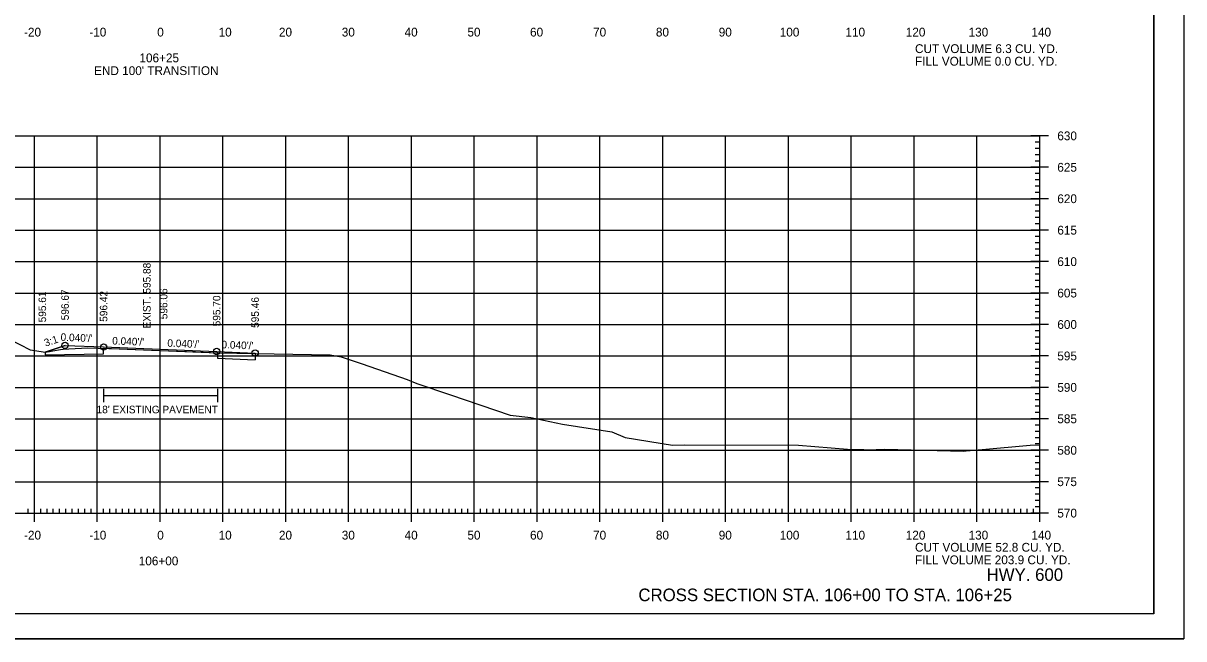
# Model space of a CAD drawing. Extents: x 961436 to 1372525, y 380079 to 2027791.
# Drawn here: x 1371173.1 to 1371357.8, y 380749.1 to 380847 of the extents above; entities that cross this region are included whole.
import ezdxf

# ---------------------------------------------------------------- set-up
doc = ezdxf.new("R2010")
doc.units = 0
for name, color, linetype in [('R_Alt Surface', 7, 'Continuous'), ('R_Axis', 7, 'Continuous'), ('R_Axis Annot', 7, 'Continuous'), ('R_Border', 7, 'Continuous'), ('R_Draft', 7, 'Continuous'), ('R_Drive', 7, 'Continuous'), ('R_Exist Surface', 7, 'Continuous'), ('R_Fin Surface', 7, 'Continuous'), ('R_Fin Surface Annot', 7, 'Continuous'), ('R_Grid', 7, 'Continuous'), ('R_No Plot', 7, 'Continuous'), ('R_Xsect Elev', 7, 'Continuous')]:
    doc.layers.add(name, color=color, linetype=linetype)

msp = doc.modelspace()

# ---------------------------------------------------------------- linework, layer by layer
at = {"layer": 'R_Alt Surface'}
for p, q in [((1371176.58, 380794.68), (1371176.58, 380794.23)), ((1371210, 380794.53), (1371210, 380793.45))]:
    msp.add_line(p, q, dxfattribs=at)
for points in [[(1371179.75, 380795.74), (1371176.58, 380794.68)], [(1371176.58, 380794.23), (1371185.86, 380794.41), (1371185.86, 380795.29), (1371194.88, 380794.95), (1371203.99, 380794.57), (1371203.99, 380793.69), (1371210, 380793.45)], [(1371210, 380794.53), (1371210, 380793.45)]]:
    msp.add_lwpolyline(points, dxfattribs=at)
at = {"layer": 'R_Axis'}
for p, q in [((1371336.28, 380829.07), (1371333.48, 380829.07)), ((1371334.88, 380769.07), (1371334.88, 380829.07)), ((1371334.88, 380828.07), (1371334.18, 380828.07)), ((1371334.88, 380827.07), (1371334.18, 380827.07)), ((1371334.88, 380826.07), (1371334.18, 380826.07)), ((1371336.28, 380824.07), (1371333.48, 380824.07)), ((1371334.88, 380825.07), (1371334.18, 380825.07)), ((1371334.88, 380823.07), (1371334.18, 380823.07)), ((1371334.88, 380822.07), (1371334.18, 380822.07)), ((1371334.88, 380821.07), (1371334.18, 380821.07)), ((1371334.88, 380820.07), (1371334.18, 380820.07)), ((1371336.28, 380819.07), (1371333.48, 380819.07)), ((1371334.88, 380818.07), (1371334.18, 380818.07)), ((1371334.88, 380817.07), (1371334.18, 380817.07)), ((1371334.88, 380816.07), (1371334.18, 380816.07)), ((1371334.88, 380815.07), (1371334.18, 380815.07)), ((1371336.28, 380814.07), (1371333.48, 380814.07)), ((1371334.88, 380813.07), (1371334.18, 380813.07)), ((1371334.88, 380812.07), (1371334.18, 380812.07)), ((1371334.88, 380811.07), (1371334.18, 380811.07)), ((1371336.28, 380809.07), (1371333.48, 380809.07)), ((1371334.88, 380810.07), (1371334.18, 380810.07)), ((1371334.88, 380808.07), (1371334.18, 380808.07)), ((1371334.88, 380807.07), (1371334.18, 380807.07)), ((1371334.88, 380806.07), (1371334.18, 380806.07)), ((1371334.88, 380805.07), (1371334.18, 380805.07)), ((1371336.28, 380804.07), (1371333.48, 380804.07)), ((1371334.88, 380803.07), (1371334.18, 380803.07)), ((1371334.88, 380802.07), (1371334.18, 380802.07)), ((1371334.88, 380801.07), (1371334.18, 380801.07)), ((1371334.88, 380800.07), (1371334.18, 380800.07)), ((1371336.28, 380799.07), (1371333.48, 380799.07)), ((1371334.88, 380798.07), (1371334.18, 380798.07)), ((1371334.88, 380797.07), (1371334.18, 380797.07)), ((1371334.88, 380796.07), (1371334.18, 380796.07)), ((1371336.28, 380794.07), (1371333.48, 380794.07)), ((1371334.88, 380795.07), (1371334.18, 380795.07)), ((1371334.88, 380793.07), (1371334.18, 380793.07)), ((1371334.88, 380792.07), (1371334.18, 380792.07)), ((1371334.88, 380791.07), (1371334.18, 380791.07)), ((1371336.28, 380789.07), (1371333.48, 380789.07)), ((1371334.88, 380790.07), (1371334.18, 380790.07)), ((1371334.88, 380788.07), (1371334.18, 380788.07)), ((1371334.88, 380787.07), (1371334.18, 380787.07)), ((1371334.88, 380786.07), (1371334.18, 380786.07)), ((1371334.88, 380785.07), (1371334.18, 380785.07)), ((1371336.28, 380784.07), (1371333.48, 380784.07)), ((1371334.88, 380783.07), (1371334.18, 380783.07)), ((1371334.88, 380782.07), (1371334.18, 380782.07)), ((1371334.88, 380781.07), (1371334.18, 380781.07)), ((1371336.28, 380779.07), (1371333.48, 380779.07)), ((1371334.88, 380780.07), (1371334.18, 380780.07)), ((1371334.88, 380778.07), (1371334.18, 380778.07)), ((1371334.88, 380777.07), (1371334.18, 380777.07)), ((1371334.88, 380776.07), (1371334.18, 380776.07)), ((1371336.28, 380774.07), (1371333.48, 380774.07)), ((1371334.88, 380775.07), (1371334.18, 380775.07)), ((1371334.88, 380773.07), (1371334.18, 380773.07)), ((1371334.88, 380772.07), (1371334.18, 380772.07)), ((1371174.88, 380767.67), (1371174.88, 380770.47)), ((1371184.88, 380767.67), (1371184.88, 380770.47)), ((1371194.88, 380767.67), (1371194.88, 380770.47)), ((1371204.88, 380767.67), (1371204.88, 380770.47)), ((1371214.88, 380767.67), (1371214.88, 380770.47)), ((1371224.88, 380767.67), (1371224.88, 380770.47)), ((1371234.88, 380767.67), (1371234.88, 380770.47)), ((1371244.88, 380767.67), (1371244.88, 380770.47)), ((1371254.88, 380767.67), (1371254.88, 380770.47)), ((1371264.88, 380767.67), (1371264.88, 380770.47)), ((1371274.88, 380767.67), (1371274.88, 380770.47)), ((1371284.88, 380767.67), (1371284.88, 380770.47)), ((1371294.88, 380767.67), (1371294.88, 380770.47)), ((1371304.88, 380767.67), (1371304.88, 380770.47)), ((1371314.88, 380767.67), (1371314.88, 380770.47)), ((1371324.88, 380767.67), (1371324.88, 380770.47)), ((1371334.88, 380771.07), (1371334.18, 380771.07)), ((1371334.88, 380770.07), (1371334.18, 380770.07)), ((1371334.88, 380767.67), (1371334.88, 380770.47)), ((1371054.88, 380769.07), (1371334.88, 380769.07)), ((1371173.88, 380769.07), (1371173.88, 380769.77)), ((1371175.88, 380769.07), (1371175.88, 380769.77)), ((1371176.88, 380769.07), (1371176.88, 380769.77)), ((1371177.88, 380769.07), (1371177.88, 380769.77)), ((1371178.88, 380769.07), (1371178.88, 380769.77)), ((1371179.88, 380769.07), (1371179.88, 380769.77)), ((1371180.88, 380769.07), (1371180.88, 380769.77)), ((1371181.88, 380769.07), (1371181.88, 380769.77)), ((1371182.88, 380769.07), (1371182.88, 380769.77)), ((1371183.88, 380769.07), (1371183.88, 380769.77)), ((1371185.88, 380769.07), (1371185.88, 380769.77)), ((1371186.88, 380769.07), (1371186.88, 380769.77)), ((1371187.88, 380769.07), (1371187.88, 380769.77)), ((1371188.88, 380769.07), (1371188.88, 380769.77)), ((1371189.88, 380769.07), (1371189.88, 380769.77)), ((1371190.88, 380769.07), (1371190.88, 380769.77)), ((1371191.88, 380769.07), (1371191.88, 380769.77)), ((1371192.88, 380769.07), (1371192.88, 380769.77)), ((1371193.88, 380769.07), (1371193.88, 380769.77)), ((1371195.88, 380769.07), (1371195.88, 380769.77)), ((1371196.88, 380769.07), (1371196.88, 380769.77)), ((1371197.88, 380769.07), (1371197.88, 380769.77)), ((1371198.88, 380769.07), (1371198.88, 380769.77)), ((1371199.88, 380769.07), (1371199.88, 380769.77)), ((1371200.88, 380769.07), (1371200.88, 380769.77)), ((1371201.88, 380769.07), (1371201.88, 380769.77)), ((1371202.88, 380769.07), (1371202.88, 380769.77)), ((1371203.88, 380769.07), (1371203.88, 380769.77)), ((1371205.88, 380769.07), (1371205.88, 380769.77)), ((1371206.88, 380769.07), (1371206.88, 380769.77)), ((1371207.88, 380769.07), (1371207.88, 380769.77)), ((1371208.88, 380769.07), (1371208.88, 380769.77)), ((1371209.88, 380769.07), (1371209.88, 380769.77)), ((1371210.88, 380769.07), (1371210.88, 380769.77)), ((1371211.88, 380769.07), (1371211.88, 380769.77)), ((1371212.88, 380769.07), (1371212.88, 380769.77)), ((1371213.88, 380769.07), (1371213.88, 380769.77)), ((1371215.88, 380769.07), (1371215.88, 380769.77)), ((1371216.88, 380769.07), (1371216.88, 380769.77)), ((1371217.88, 380769.07), (1371217.88, 380769.77)), ((1371218.88, 380769.07), (1371218.88, 380769.77)), ((1371219.88, 380769.07), (1371219.88, 380769.77)), ((1371220.88, 380769.07), (1371220.88, 380769.77)), ((1371221.88, 380769.07), (1371221.88, 380769.77)), ((1371222.88, 380769.07), (1371222.88, 380769.77)), ((1371223.88, 380769.07), (1371223.88, 380769.77)), ((1371225.88, 380769.07), (1371225.88, 380769.77)), ((1371226.88, 380769.07), (1371226.88, 380769.77)), ((1371227.88, 380769.07), (1371227.88, 380769.77)), ((1371228.88, 380769.07), (1371228.88, 380769.77)), ((1371229.88, 380769.07), (1371229.88, 380769.77)), ((1371230.88, 380769.07), (1371230.88, 380769.77)), ((1371231.88, 380769.07), (1371231.88, 380769.77)), ((1371232.88, 380769.07), (1371232.88, 380769.77)), ((1371233.88, 380769.07), (1371233.88, 380769.77)), ((1371235.88, 380769.07), (1371235.88, 380769.77)), ((1371236.88, 380769.07), (1371236.88, 380769.77)), ((1371237.88, 380769.07), (1371237.88, 380769.77)), ((1371238.88, 380769.07), (1371238.88, 380769.77)), ((1371239.88, 380769.07), (1371239.88, 380769.77)), ((1371240.88, 380769.07), (1371240.88, 380769.77)), ((1371241.88, 380769.07), (1371241.88, 380769.77)), ((1371242.88, 380769.07), (1371242.88, 380769.77)), ((1371243.88, 380769.07), (1371243.88, 380769.77)), ((1371245.88, 380769.07), (1371245.88, 380769.77)), ((1371246.88, 380769.07), (1371246.88, 380769.77)), ((1371247.88, 380769.07), (1371247.88, 380769.77)), ((1371248.88, 380769.07), (1371248.88, 380769.77)), ((1371249.88, 380769.07), (1371249.88, 380769.77)), ((1371250.88, 380769.07), (1371250.88, 380769.77)), ((1371251.88, 380769.07), (1371251.88, 380769.77)), ((1371252.88, 380769.07), (1371252.88, 380769.77)), ((1371253.88, 380769.07), (1371253.88, 380769.77)), ((1371255.88, 380769.07), (1371255.88, 380769.77)), ((1371256.88, 380769.07), (1371256.88, 380769.77)), ((1371257.88, 380769.07), (1371257.88, 380769.77)), ((1371258.88, 380769.07), (1371258.88, 380769.77)), ((1371259.88, 380769.07), (1371259.88, 380769.77)), ((1371260.88, 380769.07), (1371260.88, 380769.77)), ((1371261.88, 380769.07), (1371261.88, 380769.77)), ((1371262.88, 380769.07), (1371262.88, 380769.77)), ((1371263.88, 380769.07), (1371263.88, 380769.77)), ((1371265.88, 380769.07), (1371265.88, 380769.77)), ((1371266.88, 380769.07), (1371266.88, 380769.77)), ((1371267.88, 380769.07), (1371267.88, 380769.77)), ((1371268.88, 380769.07), (1371268.88, 380769.77)), ((1371269.88, 380769.07), (1371269.88, 380769.77)), ((1371270.88, 380769.07), (1371270.88, 380769.77)), ((1371271.88, 380769.07), (1371271.88, 380769.77)), ((1371272.88, 380769.07), (1371272.88, 380769.77)), ((1371273.88, 380769.07), (1371273.88, 380769.77)), ((1371275.88, 380769.07), (1371275.88, 380769.77)), ((1371276.88, 380769.07), (1371276.88, 380769.77)), ((1371277.88, 380769.07), (1371277.88, 380769.77)), ((1371278.88, 380769.07), (1371278.88, 380769.77)), ((1371279.88, 380769.07), (1371279.88, 380769.77)), ((1371280.88, 380769.07), (1371280.88, 380769.77)), ((1371281.88, 380769.07), (1371281.88, 380769.77)), ((1371282.88, 380769.07), (1371282.88, 380769.77)), ((1371283.88, 380769.07), (1371283.88, 380769.77)), ((1371285.88, 380769.07), (1371285.88, 380769.77)), ((1371286.88, 380769.07), (1371286.88, 380769.77)), ((1371287.88, 380769.07), (1371287.88, 380769.77)), ((1371288.88, 380769.07), (1371288.88, 380769.77)), ((1371289.88, 380769.07), (1371289.88, 380769.77)), ((1371290.88, 380769.07), (1371290.88, 380769.77)), ((1371291.88, 380769.07), (1371291.88, 380769.77)), ((1371292.88, 380769.07), (1371292.88, 380769.77)), ((1371293.88, 380769.07), (1371293.88, 380769.77)), ((1371295.88, 380769.07), (1371295.88, 380769.77)), ((1371296.88, 380769.07), (1371296.88, 380769.77)), ((1371297.88, 380769.07), (1371297.88, 380769.77)), ((1371298.88, 380769.07), (1371298.88, 380769.77)), ((1371299.88, 380769.07), (1371299.88, 380769.77)), ((1371300.88, 380769.07), (1371300.88, 380769.77)), ((1371301.88, 380769.07), (1371301.88, 380769.77)), ((1371302.88, 380769.07), (1371302.88, 380769.77)), ((1371303.88, 380769.07), (1371303.88, 380769.77)), ((1371305.88, 380769.07), (1371305.88, 380769.77)), ((1371306.88, 380769.07), (1371306.88, 380769.77)), ((1371307.88, 380769.07), (1371307.88, 380769.77)), ((1371308.88, 380769.07), (1371308.88, 380769.77)), ((1371309.88, 380769.07), (1371309.88, 380769.77)), ((1371310.88, 380769.07), (1371310.88, 380769.77)), ((1371311.88, 380769.07), (1371311.88, 380769.77)), ((1371312.88, 380769.07), (1371312.88, 380769.77)), ((1371313.88, 380769.07), (1371313.88, 380769.77)), ((1371315.88, 380769.07), (1371315.88, 380769.77)), ((1371316.88, 380769.07), (1371316.88, 380769.77)), ((1371317.88, 380769.07), (1371317.88, 380769.77)), ((1371318.88, 380769.07), (1371318.88, 380769.77)), ((1371319.88, 380769.07), (1371319.88, 380769.77)), ((1371320.88, 380769.07), (1371320.88, 380769.77)), ((1371321.88, 380769.07), (1371321.88, 380769.77)), ((1371322.88, 380769.07), (1371322.88, 380769.77)), ((1371323.88, 380769.07), (1371323.88, 380769.77)), ((1371325.88, 380769.07), (1371325.88, 380769.77)), ((1371326.88, 380769.07), (1371326.88, 380769.77)), ((1371327.88, 380769.07), (1371327.88, 380769.77)), ((1371328.88, 380769.07), (1371328.88, 380769.77)), ((1371329.88, 380769.07), (1371329.88, 380769.77)), ((1371330.88, 380769.07), (1371330.88, 380769.77)), ((1371331.88, 380769.07), (1371331.88, 380769.77)), ((1371332.88, 380769.07), (1371332.88, 380769.77)), ((1371336.28, 380769.07), (1371333.48, 380769.07)), ((1371333.88, 380769.07), (1371333.88, 380769.77))]:
    msp.add_line(p, q, dxfattribs=at)
at = {"layer": 'R_Border'}
for q in [(1371353.06, 380958.53), (1371036.88, 380753.07)]:
    msp.add_line((1371353.06, 380753.07), q, dxfattribs=at)
at = {"layer": 'R_Drive'}
for p, q in [((1371185.86, 380788.83), (1371185.86, 380786.7)), ((1371203.99, 380788.83), (1371203.99, 380786.7)), ((1371185.86, 380787.76), (1371203.99, 380787.76))]:
    msp.add_line(p, q, dxfattribs=at)
at = {"layer": 'R_Exist Surface'}
msp.add_lwpolyline([(1371170.9, 380796.75), (1371174.2, 380795.06), (1371174.94, 380794.93), (1371176.61, 380794.68), (1371177.28, 380794.78), (1371177.8, 380794.88), (1371179.04, 380795.08), (1371179.47, 380795.14), (1371180.35, 380795.21), (1371183.38, 380795.38), (1371188.35, 380795.21), (1371194.77, 380794.95), (1371200.49, 380794.73), (1371204.14, 380794.56), (1371221.94, 380794.22), (1371223.67, 380793.91), (1371227.06, 380792.82), (1371234.21, 380790.3), (1371235.73, 380789.68), (1371241.11, 380787.91), (1371250.57, 380784.63), (1371253.91, 380784.29), (1371258.91, 380783.24), (1371266.75, 380781.98), (1371268.92, 380781.12), (1371276.45, 380779.89), (1371278.29, 380779.92), (1371296.5, 380779.86), (1371304.3, 380779.27), (1371306.89, 380779.21), (1371307.42, 380779.14), (1371310.23, 380779.26), (1371322.75, 380778.91), (1371323.19, 380778.96), (1371325.71, 380779.21), (1371333.35, 380779.89), (1371334.88, 380779.94)], dxfattribs=at)
at = {"layer": 'R_Fin Surface'}
for points in [[(1371176.58, 380794.68), (1371179.75, 380795.74), (1371185.88, 380795.5), (1371203.88, 380794.78), (1371210, 380794.53), (1371210, 380793.45)], [(1371179.75, 380795.74), (1371185.88, 380795.5), (1371194.88, 380795.14), (1371203.88, 380794.78), (1371210, 380794.53)]]:
    msp.add_lwpolyline(points, dxfattribs=at)
at = {"layer": 'R_Grid'}
for p, q in [((1371054.88, 380829.07), (1371334.88, 380829.07)), ((1371174.88, 380769.07), (1371174.88, 380829.07)), ((1371184.88, 380769.07), (1371184.88, 380829.07)), ((1371194.88, 380769.07), (1371194.88, 380829.07)), ((1371204.88, 380769.07), (1371204.88, 380829.07)), ((1371214.88, 380769.07), (1371214.88, 380829.07)), ((1371224.88, 380769.07), (1371224.88, 380829.07)), ((1371234.88, 380769.07), (1371234.88, 380829.07)), ((1371244.88, 380769.07), (1371244.88, 380829.07)), ((1371254.88, 380769.07), (1371254.88, 380829.07)), ((1371264.88, 380769.07), (1371264.88, 380829.07)), ((1371274.88, 380769.07), (1371274.88, 380829.07)), ((1371284.88, 380769.07), (1371284.88, 380829.07)), ((1371294.88, 380769.07), (1371294.88, 380829.07)), ((1371304.88, 380769.07), (1371304.88, 380829.07)), ((1371314.88, 380769.07), (1371314.88, 380829.07)), ((1371324.88, 380769.07), (1371324.88, 380829.07)), ((1371334.88, 380769.07), (1371334.88, 380829.07)), ((1371054.88, 380824.07), (1371334.88, 380824.07)), ((1371054.88, 380819.07), (1371334.88, 380819.07)), ((1371054.88, 380814.07), (1371334.88, 380814.07)), ((1371054.88, 380809.07), (1371334.88, 380809.07)), ((1371054.88, 380804.07), (1371334.88, 380804.07)), ((1371054.88, 380799.07), (1371334.88, 380799.07)), ((1371054.88, 380794.07), (1371334.88, 380794.07)), ((1371054.88, 380789.07), (1371334.88, 380789.07)), ((1371054.88, 380784.07), (1371334.88, 380784.07)), ((1371054.88, 380779.07), (1371334.88, 380779.07)), ((1371054.88, 380774.07), (1371334.88, 380774.07)), ((1371054.88, 380769.07), (1371334.88, 380769.07))]:
    msp.add_line(p, q, dxfattribs=at)
at = {"layer": 'R_No Plot'}
msp.add_line((1371024.48, 380749.09), (1371357.81, 380749.09), dxfattribs=at)
for points in [[(1371024.47, 380962.43), (1371357.81, 380962.43), (1371357.81, 380749.09), (1371024.47, 380749.09)], [(1371270.8, 380958.53), (1371290.42, 380958.53), (1371290.42, 380948.65), (1371306.53, 380948.65), (1371329.73, 380948.65), (1371329.85, 380920.5), (1371353.06, 380920.5), (1371353.06, 380753.07), (1371036.88, 380753.07), (1371036.88, 380958.53)]]:
    msp.add_lwpolyline(points, close=True, dxfattribs=at)
for centre in [(1371179.75, 380795.74), (1371185.88, 380795.5), (1371203.88, 380794.78), (1371210, 380794.53)]:
    msp.add_circle(centre, 0.5, dxfattribs=at)

# ---------------------------------------------------------------- texts
at = {"layer": 'R_Axis Annot'}
for s, p in [('-20', (1371173.22, 380844.87)), ('-10', (1371183.61, 380844.87)), ('0', (1371194.42, 380844.87)), ('10', (1371204.19, 380844.87)), ('20', (1371213.79, 380844.87)), ('30', (1371223.79, 380844.87)), ('40', (1371233.79, 380844.87)), ('50', (1371243.79, 380844.87)), ('60', (1371253.76, 380844.87)), ('70', (1371263.79, 380844.87)), ('80', (1371273.79, 380844.87)), ('90', (1371283.79, 380844.87)), ('100', (1371293.5, 380844.87)), ('110', (1371303.96, 380844.87)), ('120', (1371313.56, 380844.87)), ('130', (1371323.56, 380844.87)), ('140', (1371333.56, 380844.87)), ('106+25', (1371191.59, 380840.77)), ('CUT VOLUME 6.3 CU. YD.', (1371315.03, 380842.24)), ("END 100' TRANSITION", (1371184.37, 380838.74)), ('FILL VOLUME 0.0 CU. YD.', (1371315.03, 380840.24)), ('630', (1371337.68, 380828.37)), ('625', (1371337.68, 380823.37)), ('620', (1371337.68, 380818.37)), ('615', (1371337.68, 380813.37)), ('610', (1371337.68, 380808.37)), ('605', (1371337.68, 380803.37)), ('600', (1371337.68, 380798.37)), ('595', (1371337.68, 380793.37)), ('590', (1371337.68, 380788.37)), ('585', (1371337.68, 380783.37)), ('580', (1371337.68, 380778.37)), ('575', (1371337.68, 380773.37)), ('570', (1371337.68, 380768.37)), ('-20', (1371173.22, 380764.87)), ('-10', (1371183.61, 380764.87)), ('0', (1371194.42, 380764.87)), ('10', (1371204.19, 380764.87)), ('20', (1371213.79, 380764.87)), ('30', (1371223.79, 380764.87)), ('40', (1371233.79, 380764.87)), ('50', (1371243.79, 380764.87)), ('60', (1371253.76, 380764.87)), ('70', (1371263.79, 380764.87)), ('80', (1371273.79, 380764.87)), ('90', (1371283.79, 380764.87)), ('100', (1371293.5, 380764.87)), ('110', (1371303.96, 380764.87)), ('120', (1371313.56, 380764.87)), ('130', (1371323.56, 380764.87)), ('140', (1371333.56, 380764.87)), ('CUT VOLUME 52.8 CU. YD.', (1371315.03, 380762.94)), ('106+00', (1371191.48, 380760.77)), ('FILL VOLUME 203.9 CU. YD.', (1371315.03, 380760.94))]:
    msp.add_text(s, height=1.4, dxfattribs=at).set_placement(p)
at = {"layer": 'R_Draft'}
for s, p in [('HWY. 600', (1371326.42, 380758.29)), ('CROSS SECTION STA. 106+00 TO STA. 106+25', (1371271, 380755.07))]:
    msp.add_text(s, height=2, dxfattribs=at).set_placement(p)
at = {"layer": 'R_Fin Surface Annot'}
for s, rotation, p in [('595.61', 90, (1371176.73, 380799.41)), ('596.67', 90, (1371180.35, 380799.74)), ('596.42', 90, (1371186.48, 380799.5)), ('596.06', 90, (1371196.04, 380799.91)), ('595.70', 90, (1371204.48, 380798.78)), ('595.46', 90, (1371210.6, 380798.53)), ("0.040'/'", 357.7094, (1371179.02, 380796.48)), ('3:1', 18.4349, (1371176.64, 380795.53)), ("0.040'/'", 357.7094, (1371187.23, 380795.9)), ("0.040'/'", 357.7094, (1371196.01, 380795.54)), ("0.040'/'", 357.7094, (1371204.62, 380795.3))]:
    msp.add_text(s, height=1.2, rotation=rotation, dxfattribs=at).set_placement(p)
msp.add_text("18' EXISTING PAVEMENT", height=1.2, dxfattribs=at).set_placement((1371184.77, 380784.95))
at = {"layer": 'R_Xsect Elev'}
msp.add_text('EXIST. 595.88', height=1.2, rotation=90, dxfattribs=at).set_placement((1371193.37, 380798.45))

doc.saveas('drawing.dxf')
